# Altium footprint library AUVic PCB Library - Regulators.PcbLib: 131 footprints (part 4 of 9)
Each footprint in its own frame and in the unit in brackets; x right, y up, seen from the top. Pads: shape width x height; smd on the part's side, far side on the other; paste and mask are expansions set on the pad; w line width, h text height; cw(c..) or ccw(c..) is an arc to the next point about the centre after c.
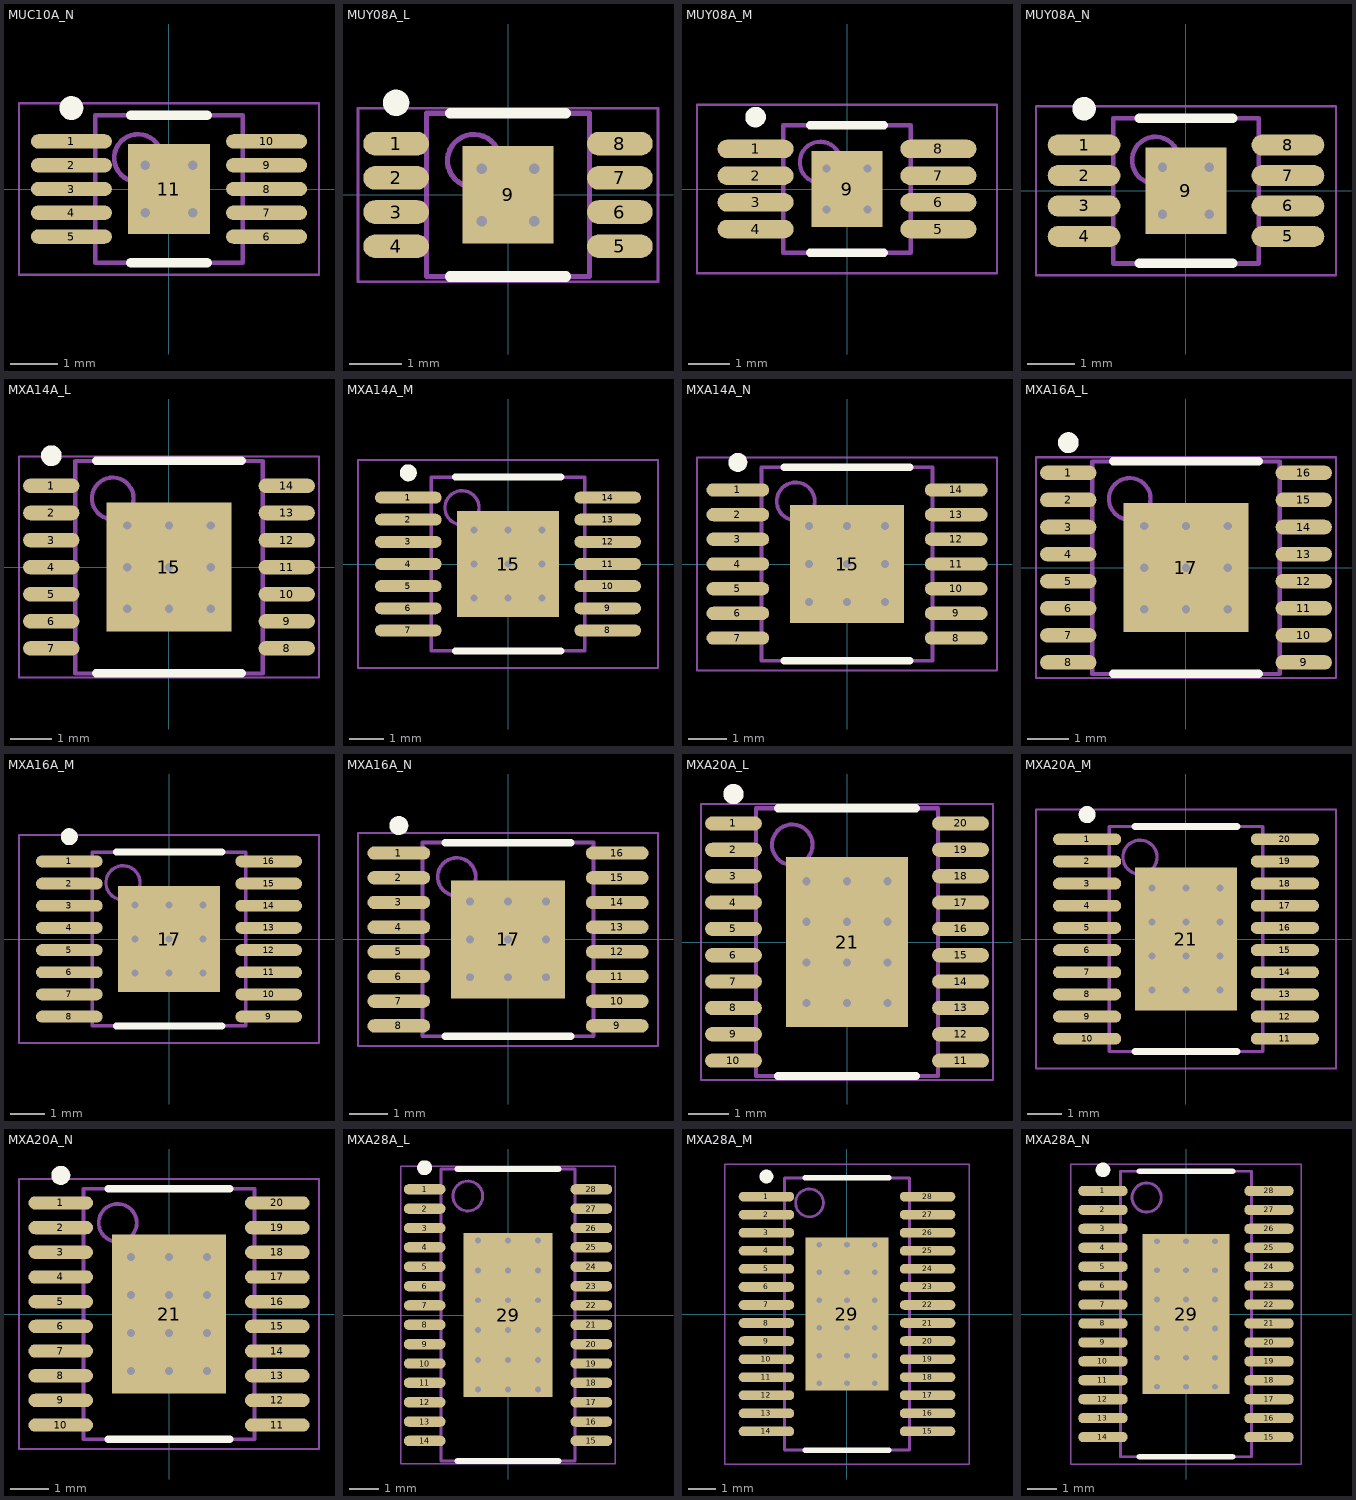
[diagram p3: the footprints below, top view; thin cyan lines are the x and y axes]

## MUC10A_N [mm] "TSSOP, 10-Leads, Body 3x3mm, Pitch 0.5mm, Exposed Pad, IPC Medium Density"
height 1.1
pads (11):
  oval 1.7x0.3 smd: 1(-2.05,1) 2(-2.05,0.5) 3(-2.05,0) 4(-2.05,-0.5) 5(-2.05,-1) 6(2.05,-1) 7(2.05,-0.5) 8(2.05,0) 9(2.05,0.5) 10(2.05,1)
  rect 1.73x1.9 smd: 11(0,0)
via 0.5,-0.5 diameter 0.4 hole 0.2
via -0.5,-0.5 diameter 0.4 hole 0.2
via 0.5,0.5 diameter 0.4 hole 0.2
via -0.5,0.5 diameter 0.4 hole 0.2
Top Overlay:
  circle w0.25: c-2.05,1.7 r0.125
  lines w0.2: -0.8,-1.55 0.8,-1.55 ; -0.8,1.55 0.8,1.55
Mechanical 13:
  circle w0.1: c-0.65,0.65 r0.5
  lines w0.1: -1.55,-1.55 -1.55,1.55 1.55,1.55 1.55,-1.55 -1.55,-1.55
Mechanical 15:
  lines w0.05: -3.15,-1.8 -3.15,1.8 3.15,1.8 3.15,-1.8 -3.15,-1.8
  lines w0.1: -0.5,0 0.5,0 ; 0,-0.5 0,0.5
3D body: height 1.1, standoff 0.05, extent -1.55,-1.55 1.55,1.55

## MUY08A_L [mm] "TSOP, 8-Leads, Body 3x3mm, Pitch 0.65mm, Thermal Pad, IPC High Density"
height 1.09
pads (9):
  oval 1.25x0.45 smd: 1(-2.125,0.975) 2(-2.125,0.325) 3(-2.125,-0.325) 4(-2.125,-0.975) 5(2.125,-0.975) 6(2.125,-0.325) 7(2.125,0.325) 8(2.125,0.975)
  rect 1.73x1.85 smd: 9(0,0)
via -0.5,0.5 diameter 0.4 hole 0.2
via 0.5,0.5 diameter 0.4 hole 0.2
via -0.5,-0.5 diameter 0.4 hole 0.2
via 0.5,-0.5 diameter 0.4 hole 0.2
Top Overlay:
  circle w0.25: c-2.125,1.75 r0.125
  lines w0.2: -1.1,-1.55 1.1,-1.55 ; -1.1,1.55 1.1,1.55
Mechanical 13:
  circle w0.1: c-0.65,0.65 r0.5
  lines w0.1: -1.55,-1.55 -1.55,1.55 1.55,1.55 1.55,-1.55 -1.55,-1.55
Mechanical 15:
  lines w0.05: -2.85,-1.65 -2.85,1.65 2.85,1.65 2.85,-1.65 -2.85,-1.65
  lines w0.1: -0.5,0 0.5,0 ; 0,-0.5 0,0.5
3D body: height 1.09, standoff 0.06, extent -1.55,-1.55 1.55,1.55

## MUY08A_M [mm] "TSOP, 8-Leads, Body 3x3mm, Pitch 0.65mm, Thermal Pad, IPC Low Density"
height 1.09
pads (9):
  oval 1.85x0.45 smd: 1(-2.225,0.975) 2(-2.225,0.325) 3(-2.225,-0.325) 4(-2.225,-0.975) 5(2.225,-0.975) 6(2.225,-0.325) 7(2.225,0.325) 8(2.225,0.975)
  rect 1.73x1.85 smd: 9(0,0)
via -0.5,0.5 diameter 0.4 hole 0.2
via 0.5,0.5 diameter 0.4 hole 0.2
via -0.5,-0.5 diameter 0.4 hole 0.2
via 0.5,-0.5 diameter 0.4 hole 0.2
Top Overlay:
  circle w0.25: c-2.225,1.75 r0.125
  lines w0.2: -0.9,-1.55 0.9,-1.55 ; -0.9,1.55 0.9,1.55
Mechanical 13:
  circle w0.1: c-0.65,0.65 r0.5
  lines w0.1: -1.55,-1.55 -1.55,1.55 1.55,1.55 1.55,-1.55 -1.55,-1.55
Mechanical 15:
  lines w0.05: -3.65,-2.05 -3.65,2.05 3.65,2.05 3.65,-2.05 -3.65,-2.05
  lines w0.1: -0.5,0 0.5,0 ; 0,-0.5 0,0.5
3D body: height 1.09, standoff 0.06, extent -1.55,-1.55 1.55,1.55

## MUY08A_N [mm] "TSOP, 8-Leads, Body 3x3mm, Pitch 0.65mm, Thermal Pad, IPC Medium Density"
height 1.09
pads (9):
  oval 1.55x0.45 smd: 1(-2.175,0.975) 2(-2.175,0.325) 3(-2.175,-0.325) 4(-2.175,-0.975) 5(2.175,-0.975) 6(2.175,-0.325) 7(2.175,0.325) 8(2.175,0.975)
  rect 1.73x1.85 smd: 9(0,0)
via 0.5,-0.5 diameter 0.4 hole 0.2
via -0.5,-0.5 diameter 0.4 hole 0.2
via 0.5,0.5 diameter 0.4 hole 0.2
via -0.5,0.5 diameter 0.4 hole 0.2
Top Overlay:
  circle w0.25: c-2.175,1.75 r0.125
  lines w0.2: -1,-1.55 1,-1.55 ; -1,1.55 1,1.55
Mechanical 13:
  circle w0.1: c-0.65,0.65 r0.5
  lines w0.1: -1.55,-1.55 1.55,-1.55 1.55,1.55 -1.55,1.55 -1.55,-1.55
Mechanical 15:
  lines w0.05: -3.2,-1.8 3.2,-1.8 3.2,1.8 -3.2,1.8 -3.2,-1.8
  lines w0.1: -0.5,0 0.5,0 ; 0,-0.5 0,0.5
3D body: height 1.09, standoff 0.06, extent -1.55,-1.55 1.55,1.55

## MXA14A_L [mm] "TSOP, 14-Leads, Body 5x4.4mm, Pitch 0.65mm, Thermal Pad, IPC High Density"
height 1.1
pads (15):
  oval 1.35x0.35 smd: 1(-2.825,1.95) 2(-2.825,1.3) 3(-2.825,0.65) 4(-2.825,0) 5(-2.825,-0.65) 6(-2.825,-1.3) 7(-2.825,-1.95) 8(2.825,-1.95) 9(2.825,-1.3) 10(2.825,-0.65) 11(2.825,0) 12(2.825,0.65) 13(2.825,1.3) 14(2.825,1.95)
  rect 3x3.1 smd: 15(0,0)
via 1,1 diameter 0.4 hole 0.2
via 1,-1 diameter 0.4 hole 0.2
via 1,0 diameter 0.4 hole 0.2
via -1,1 diameter 0.4 hole 0.2
via 0,1 diameter 0.4 hole 0.2
via 0,-1 diameter 0.4 hole 0.2
via -1,-1 diameter 0.4 hole 0.2
via 0,0 diameter 0.4 hole 0.2
via -1,0 diameter 0.4 hole 0.2
Top Overlay:
  circle w0.25: c-2.825,2.675 r0.125
  lines w0.2: -1.75,-2.55 1.75,-2.55 ; -1.75,2.55 1.75,2.55
Mechanical 13:
  circle w0.1: c-1.35,1.65 r0.5
  lines w0.1: -2.25,-2.55 2.25,-2.55 2.25,2.55 -2.25,2.55 -2.25,-2.55
Mechanical 15:
  lines w0.05: -3.6,-2.65 3.6,-2.65 3.6,2.65 -3.6,2.65 -3.6,-2.65
  lines w0.1: -0.5,0 0.5,0 ; 0,-0.5 0,0.5
3D body: height 1.1, standoff 0.05, extent -2.25,-2.55 2.25,2.55

## MXA14A_M [mm] "TSOP, 14-Leads, Body 5x4.4mm, Pitch 0.65mm, Thermal Pad, IPC Low Density"
height 1.1
pads (15):
  oval 1.95x0.35 smd: 1(-2.925,1.95) 2(-2.925,1.3) 3(-2.925,0.65) 4(-2.925,0) 5(-2.925,-0.65) 6(-2.925,-1.3) 7(-2.925,-1.95) 8(2.925,-1.95) 9(2.925,-1.3) 10(2.925,-0.65) 11(2.925,0) 12(2.925,0.65) 13(2.925,1.3) 14(2.925,1.95)
  rect 3x3.1 smd: 15(0,0)
via -1,0 diameter 0.4 hole 0.2
via 0,0 diameter 0.4 hole 0.2
via -1,-1 diameter 0.4 hole 0.2
via 0,-1 diameter 0.4 hole 0.2
via 0,1 diameter 0.4 hole 0.2
via -1,1 diameter 0.4 hole 0.2
via 1,0 diameter 0.4 hole 0.2
via 1,-1 diameter 0.4 hole 0.2
via 1,1 diameter 0.4 hole 0.2
Top Overlay:
  circle w0.25: c-2.925,2.675 r0.125
  lines w0.2: -1.55,-2.55 1.55,-2.55 ; -1.55,2.55 1.55,2.55
Mechanical 13:
  circle w0.1: c-1.35,1.65 r0.5
  lines w0.1: -2.25,-2.55 -2.25,2.55 2.25,2.55 2.25,-2.55 -2.25,-2.55
Mechanical 15:
  lines w0.05: -4.4,-3.05 -4.4,3.05 4.4,3.05 4.4,-3.05 -4.4,-3.05
  lines w0.1: -0.5,0 0.5,0 ; 0,-0.5 0,0.5
3D body: height 1.1, standoff 0.05, extent -2.25,-2.55 2.25,2.55

## MXA14A_N [mm] "TSOP, 14-Leads, Body 5x4.4mm, Pitch 0.65mm, Thermal Pad, IPC Medium Density"
height 1.1
pads (15):
  oval 1.65x0.35 smd: 1(-2.875,1.95) 2(-2.875,1.3) 3(-2.875,0.65) 4(-2.875,0) 5(-2.875,-0.65) 6(-2.875,-1.3) 7(-2.875,-1.95) 8(2.875,-1.95) 9(2.875,-1.3) 10(2.875,-0.65) 11(2.875,0) 12(2.875,0.65) 13(2.875,1.3) 14(2.875,1.95)
  rect 3x3.1 smd: 15(0,0)
via -1,0 diameter 0.4 hole 0.2
via 0,0 diameter 0.4 hole 0.2
via -1,-1 diameter 0.4 hole 0.2
via 0,-1 diameter 0.4 hole 0.2
via 0,1 diameter 0.4 hole 0.2
via -1,1 diameter 0.4 hole 0.2
via 1,0 diameter 0.4 hole 0.2
via 1,-1 diameter 0.4 hole 0.2
via 1,1 diameter 0.4 hole 0.2
Top Overlay:
  circle w0.25: c-2.875,2.675 r0.125
  lines w0.2: -1.65,-2.55 1.65,-2.55 ; -1.65,2.55 1.65,2.55
Mechanical 13:
  circle w0.1: c-1.35,1.65 r0.5
  lines w0.1: -2.25,-2.55 -2.25,2.55 2.25,2.55 2.25,-2.55 -2.25,-2.55
Mechanical 15:
  lines w0.05: -3.95,-2.8 -3.95,2.8 3.95,2.8 3.95,-2.8 -3.95,-2.8
  lines w0.1: -0.5,0 0.5,0 ; 0,-0.5 0,0.5
3D body: height 1.1, standoff 0.05, extent -2.25,-2.55 2.25,2.55

## MXA16A_L [mm] "TSOP, 16-Leads, Body 5x4.4mm, Pitch 0.65mm, Thermal Pad, IPC High Density"
height 1.1
pads (17):
  oval 1.35x0.35 smd: 1(-2.825,2.275) 2(-2.825,1.625) 3(-2.825,0.975) 4(-2.825,0.325) 5(-2.825,-0.325) 6(-2.825,-0.975) 7(-2.825,-1.625) 8(-2.825,-2.275) 9(2.825,-2.275) 10(2.825,-1.625) 11(2.825,-0.975) 12(2.825,-0.325) 13(2.825,0.325) 14(2.825,0.975) 15(2.825,1.625) 16(2.825,2.275)
  rect 3x3.1 smd: 17(0,0)
via 1,1 diameter 0.4 hole 0.2
via 1,-1 diameter 0.4 hole 0.2
via 1,0 diameter 0.4 hole 0.2
via -1,1 diameter 0.4 hole 0.2
via 0,1 diameter 0.4 hole 0.2
via 0,-1 diameter 0.4 hole 0.2
via -1,-1 diameter 0.4 hole 0.2
via 0,0 diameter 0.4 hole 0.2
via -1,0 diameter 0.4 hole 0.2
Top Overlay:
  circle w0.25: c-2.825,3 r0.125
  lines w0.2: -1.75,-2.55 1.75,-2.55 ; -1.75,2.55 1.75,2.55
Mechanical 13:
  circle w0.1: c-1.35,1.65 r0.5
  lines w0.1: -2.25,-2.55 2.25,-2.55 2.25,2.55 -2.25,2.55 -2.25,-2.55
Mechanical 15:
  lines w0.05: -3.6,-2.65 3.6,-2.65 3.6,2.65 -3.6,2.65 -3.6,-2.65
  lines w0.1: -0.5,0 0.5,0 ; 0,-0.5 0,0.5
3D body: height 1.1, standoff 0.05, extent -2.25,-2.55 2.25,2.55

## MXA16A_M [mm] "TSOP, 16-Leads, Body 5x4.4mm, Pitch 0.65mm, Thermal Pad, IPC Low Density"
height 1.1
pads (17):
  oval 1.95x0.35 smd: 1(-2.925,2.275) 2(-2.925,1.625) 3(-2.925,0.975) 4(-2.925,0.325) 5(-2.925,-0.325) 6(-2.925,-0.975) 7(-2.925,-1.625) 8(-2.925,-2.275) 9(2.925,-2.275) 10(2.925,-1.625) 11(2.925,-0.975) 12(2.925,-0.325) 13(2.925,0.325) 14(2.925,0.975) 15(2.925,1.625) 16(2.925,2.275)
  rect 3x3.1 smd: 17(0,0)
via -1,0 diameter 0.4 hole 0.2
via 0,0 diameter 0.4 hole 0.2
via -1,-1 diameter 0.4 hole 0.2
via 0,-1 diameter 0.4 hole 0.2
via 0,1 diameter 0.4 hole 0.2
via -1,1 diameter 0.4 hole 0.2
via 1,0 diameter 0.4 hole 0.2
via 1,-1 diameter 0.4 hole 0.2
via 1,1 diameter 0.4 hole 0.2
Top Overlay:
  circle w0.25: c-2.925,3 r0.125
  lines w0.2: -1.55,-2.55 1.55,-2.55 ; -1.55,2.55 1.55,2.55
Mechanical 13:
  circle w0.1: c-1.35,1.65 r0.5
  lines w0.1: -2.25,-2.55 -2.25,2.55 2.25,2.55 2.25,-2.55 -2.25,-2.55
Mechanical 15:
  lines w0.05: -4.4,-3.05 -4.4,3.05 4.4,3.05 4.4,-3.05 -4.4,-3.05
  lines w0.1: -0.5,0 0.5,0 ; 0,-0.5 0,0.5
3D body: height 1.1, standoff 0.05, extent -2.25,-2.55 2.25,2.55

## MXA16A_N [mm] "TSOP, 16-Leads, Body 5x4.4mm, Pitch 0.65mm, Thermal Pad, IPC Medium Density"
height 1.1
pads (17):
  oval 1.65x0.35 smd: 1(-2.875,2.275) 2(-2.875,1.625) 3(-2.875,0.975) 4(-2.875,0.325) 5(-2.875,-0.325) 6(-2.875,-0.975) 7(-2.875,-1.625) 8(-2.875,-2.275) 9(2.875,-2.275) 10(2.875,-1.625) 11(2.875,-0.975) 12(2.875,-0.325) 13(2.875,0.325) 14(2.875,0.975) 15(2.875,1.625) 16(2.875,2.275)
  rect 3x3.1 smd: 17(0,0)
via -1,0 diameter 0.4 hole 0.2
via 0,0 diameter 0.4 hole 0.2
via -1,-1 diameter 0.4 hole 0.2
via 0,-1 diameter 0.4 hole 0.2
via 0,1 diameter 0.4 hole 0.2
via -1,1 diameter 0.4 hole 0.2
via 1,0 diameter 0.4 hole 0.2
via 1,-1 diameter 0.4 hole 0.2
via 1,1 diameter 0.4 hole 0.2
Top Overlay:
  circle w0.25: c-2.875,3 r0.125
  lines w0.2: -1.65,-2.55 1.65,-2.55 ; -1.65,2.55 1.65,2.55
Mechanical 13:
  circle w0.1: c-1.35,1.65 r0.5
  lines w0.1: -2.25,-2.55 -2.25,2.55 2.25,2.55 2.25,-2.55 -2.25,-2.55
Mechanical 15:
  lines w0.05: -3.95,-2.8 -3.95,2.8 3.95,2.8 3.95,-2.8 -3.95,-2.8
  lines w0.1: -0.5,0 0.5,0 ; 0,-0.5 0,0.5
3D body: height 1.1, standoff 0.05, extent -2.25,-2.55 2.25,2.55

## MXA20A_L [mm] "TSOP, 20-Leads, Body 6.5x4.4mm, Pitch 0.65mm, Thermal Pad, IPC High Density"
height 1.1
pads (21):
  oval 1.4x0.35 smd: 1(-2.8,2.925) 2(-2.8,2.275) 3(-2.8,1.625) 4(-2.8,0.975) 5(-2.8,0.325) 6(-2.8,-0.325) 7(-2.8,-0.975) 8(-2.8,-1.625) 9(-2.8,-2.275) 10(-2.8,-2.925) 11(2.8,-2.925) 12(2.8,-2.275) 13(2.8,-1.625) 14(2.8,-0.975) 15(2.8,-0.325) 16(2.8,0.325) 17(2.8,0.975) 18(2.8,1.625) 19(2.8,2.275) 20(2.8,2.925)
  rect 3x4.2 smd: 21(0,0)
via 0,1.5 diameter 0.5 hole 0.2
via 1,1.5 diameter 0.5 hole 0.2
via -1,1.5 diameter 0.5 hole 0.2
via -1,0.5 diameter 0.5 hole 0.2
via -1,-0.5 diameter 0.5 hole 0.2
via -1,-1.5 diameter 0.5 hole 0.2
via 1,-1.5 diameter 0.5 hole 0.2
via 0,-1.5 diameter 0.5 hole 0.2
via 1,-0.5 diameter 0.5 hole 0.2
via 0,-0.5 diameter 0.5 hole 0.2
via 1,0.5 diameter 0.5 hole 0.2
via 0,0.5 diameter 0.5 hole 0.2
Top Overlay:
  circle w0.25: c-2.8,3.65 r0.125
  lines w0.2: -1.7,-3.3 1.7,-3.3 ; -1.7,3.3 1.7,3.3
Mechanical 13:
  circle w0.1: c-1.35,2.4 r0.5
  lines w0.1: -2.25,-3.3 -2.25,3.3 2.25,3.3 2.25,-3.3 -2.25,-3.3
Mechanical 15:
  lines w0.05: -3.6,-3.4 -3.6,3.4 3.6,3.4 3.6,-3.4 -3.6,-3.4
  lines w0.1: -0.5,0 0.5,0 ; 0,-0.5 0,0.5
3D body: height 1.1, standoff 0.05, extent -2.25,-3.3 2.25,3.3

## MXA20A_M [mm] "TSOP, 20-Leads, Body 6.5x4.4mm, Pitch 0.65mm, Thermal Pad, IPC Low Density"
height 1.1
pads (21):
  oval 2x0.35 smd: 1(-2.9,2.925) 2(-2.9,2.275) 3(-2.9,1.625) 4(-2.9,0.975) 5(-2.9,0.325) 6(-2.9,-0.325) 7(-2.9,-0.975) 8(-2.9,-1.625) 9(-2.9,-2.275) 10(-2.9,-2.925) 11(2.9,-2.925) 12(2.9,-2.275) 13(2.9,-1.625) 14(2.9,-0.975) 15(2.9,-0.325) 16(2.9,0.325) 17(2.9,0.975) 18(2.9,1.625) 19(2.9,2.275) 20(2.9,2.925)
  rect 3x4.2 smd: 21(0,0)
via 0,0.5 diameter 0.5 hole 0.2
via 1,0.5 diameter 0.5 hole 0.2
via 0,-0.5 diameter 0.5 hole 0.2
via 1,-0.5 diameter 0.5 hole 0.2
via 0,-1.5 diameter 0.5 hole 0.2
via 1,-1.5 diameter 0.5 hole 0.2
via -1,-1.5 diameter 0.5 hole 0.2
via -1,-0.5 diameter 0.5 hole 0.2
via -1,0.5 diameter 0.5 hole 0.2
via -1,1.5 diameter 0.5 hole 0.2
via 1,1.5 diameter 0.5 hole 0.2
via 0,1.5 diameter 0.5 hole 0.2
Top Overlay:
  circle w0.25: c-2.9,3.65 r0.125
  lines w0.2: -1.5,-3.3 1.5,-3.3 ; -1.5,3.3 1.5,3.3
Mechanical 13:
  circle w0.1: c-1.35,2.4 r0.5
  lines w0.1: -2.25,-3.3 2.25,-3.3 2.25,3.3 -2.25,3.3 -2.25,-3.3
Mechanical 15:
  lines w0.05: -4.4,-3.8 4.4,-3.8 4.4,3.8 -4.4,3.8 -4.4,-3.8
  lines w0.1: -0.5,0 0.5,0 ; 0,-0.5 0,0.5
3D body: height 1.1, standoff 0.05, extent -2.25,-3.3 2.25,3.3

## MXA20A_N [mm] "TSOP, 20-Leads, Body 6.5x4.4mm, Pitch 0.65mm, Thermal Pad, IPC Medium Density"
height 1.1
pads (21):
  oval 1.7x0.35 smd: 1(-2.85,2.925) 2(-2.85,2.275) 3(-2.85,1.625) 4(-2.85,0.975) 5(-2.85,0.325) 6(-2.85,-0.325) 7(-2.85,-0.975) 8(-2.85,-1.625) 9(-2.85,-2.275) 10(-2.85,-2.925) 11(2.85,-2.925) 12(2.85,-2.275) 13(2.85,-1.625) 14(2.85,-0.975) 15(2.85,-0.325) 16(2.85,0.325) 17(2.85,0.975) 18(2.85,1.625) 19(2.85,2.275) 20(2.85,2.925)
  rect 3x4.2 smd: 21(0,0)
via 0,1.5 diameter 0.5 hole 0.2
via 1,1.5 diameter 0.5 hole 0.2
via -1,1.5 diameter 0.5 hole 0.2
via -1,0.5 diameter 0.5 hole 0.2
via -1,-0.5 diameter 0.5 hole 0.2
via -1,-1.5 diameter 0.5 hole 0.2
via 1,-1.5 diameter 0.5 hole 0.2
via 0,-1.5 diameter 0.5 hole 0.2
via 1,-0.5 diameter 0.5 hole 0.2
via 0,-0.5 diameter 0.5 hole 0.2
via 1,0.5 diameter 0.5 hole 0.2
via 0,0.5 diameter 0.5 hole 0.2
Top Overlay:
  circle w0.25: c-2.85,3.65 r0.125
  lines w0.2: -1.6,-3.3 1.6,-3.3 ; -1.6,3.3 1.6,3.3
Mechanical 13:
  circle w0.1: c-1.35,2.4 r0.5
  lines w0.1: -2.25,-3.3 2.25,-3.3 2.25,3.3 -2.25,3.3 -2.25,-3.3
Mechanical 15:
  lines w0.05: -3.95,-3.55 3.95,-3.55 3.95,3.55 -3.95,3.55 -3.95,-3.55
  lines w0.1: -0.5,0 0.5,0 ; 0,-0.5 0,0.5
3D body: height 1.1, standoff 0.05, extent -2.25,-3.3 2.25,3.3

## MXA28A_L [mm] "TSOP, 28-Leads, Body 9.7x4.4mm, Pitch 0.65mm, Thermal Pad, IPC High Density"
height 1.1
pads (29):
  oval 1.4x0.35 smd: 1(-2.8,4.225) 2(-2.8,3.575) 3(-2.8,2.925) 4(-2.8,2.275) 5(-2.8,1.625) 6(-2.8,0.975) 7(-2.8,0.325) 8(-2.8,-0.325) 9(-2.8,-0.975) 10(-2.8,-1.625) 11(-2.8,-2.275) 12(-2.8,-2.925) 13(-2.8,-3.575) 14(-2.8,-4.225) 15(2.8,-4.225) 16(2.8,-3.575) 17(2.8,-2.925) 18(2.8,-2.275) 19(2.8,-1.625) 20(2.8,-0.975) 21(2.8,-0.325) 22(2.8,0.325) 23(2.8,0.975) 24(2.8,1.625) 25(2.8,2.275) 26(2.8,2.925) 27(2.8,3.575) 28(2.8,4.225)
  rect 3x5.5 smd: 29(0,0)
via 0,0.5 diameter 0.4 hole 0.2
via 1,0.5 diameter 0.4 hole 0.2
via 0,-0.5 diameter 0.4 hole 0.2
via 1,-0.5 diameter 0.4 hole 0.2
via 0,-1.5 diameter 0.4 hole 0.2
via 1,-1.5 diameter 0.4 hole 0.2
via 1,1.5 diameter 0.4 hole 0.2
via 0,1.5 diameter 0.4 hole 0.2
via 1,-2.5 diameter 0.4 hole 0.2
via 0,-2.5 diameter 0.4 hole 0.2
via -1,-2.5 diameter 0.4 hole 0.2
via -1,1.5 diameter 0.4 hole 0.2
via -1,-1.5 diameter 0.4 hole 0.2
via -1,-0.5 diameter 0.4 hole 0.2
via -1,0.5 diameter 0.4 hole 0.2
via -1,2.5 diameter 0.4 hole 0.2
via 0,2.5 diameter 0.4 hole 0.2
via 1,2.5 diameter 0.4 hole 0.2
Top Overlay:
  circle w0.25: c-2.8,4.95 r0.125
  lines w0.2: -1.7,-4.9 1.7,-4.9 ; -1.7,4.9 1.7,4.9
Mechanical 13:
  circle w0.1: c-1.35,4 r0.5
  lines w0.1: -2.25,-4.9 2.25,-4.9 2.25,4.9 -2.25,4.9 -2.25,-4.9
Mechanical 15:
  lines w0.05: -3.6,-5 3.6,-5 3.6,5 -3.6,5 -3.6,-5
  lines w0.1: -0.5,0 0.5,0 ; 0,-0.5 0,0.5
3D body: height 1.1, standoff 0.05, extent -2.25,-4.9 2.25,4.9

## MXA28A_M [mm] "TSOP, 28-Leads, Body 9.7x4.4mm, Pitch 0.65mm, Thermal Pad, IPC Low Density"
height 1.1
pads (29):
  oval 2x0.35 smd: 1(-2.9,4.225) 2(-2.9,3.575) 3(-2.9,2.925) 4(-2.9,2.275) 5(-2.9,1.625) 6(-2.9,0.975) 7(-2.9,0.325) 8(-2.9,-0.325) 9(-2.9,-0.975) 10(-2.9,-1.625) 11(-2.9,-2.275) 12(-2.9,-2.925) 13(-2.9,-3.575) 14(-2.9,-4.225) 15(2.9,-4.225) 16(2.9,-3.575) 17(2.9,-2.925) 18(2.9,-2.275) 19(2.9,-1.625) 20(2.9,-0.975) 21(2.9,-0.325) 22(2.9,0.325) 23(2.9,0.975) 24(2.9,1.625) 25(2.9,2.275) 26(2.9,2.925) 27(2.9,3.575) 28(2.9,4.225)
  rect 3x5.5 smd: 29(0,0)
via 0,0.5 diameter 0.4 hole 0.2
via 1,0.5 diameter 0.4 hole 0.2
via 0,-0.5 diameter 0.4 hole 0.2
via 1,-0.5 diameter 0.4 hole 0.2
via 0,-1.5 diameter 0.4 hole 0.2
via 1,-1.5 diameter 0.4 hole 0.2
via 1,1.5 diameter 0.4 hole 0.2
via 0,1.5 diameter 0.4 hole 0.2
via 1,-2.5 diameter 0.4 hole 0.2
via 0,-2.5 diameter 0.4 hole 0.2
via -1,-2.5 diameter 0.4 hole 0.2
via -1,1.5 diameter 0.4 hole 0.2
via -1,-1.5 diameter 0.4 hole 0.2
via -1,-0.5 diameter 0.4 hole 0.2
via -1,0.5 diameter 0.4 hole 0.2
via -1,2.5 diameter 0.4 hole 0.2
via 0,2.5 diameter 0.4 hole 0.2
via 1,2.5 diameter 0.4 hole 0.2
Top Overlay:
  circle w0.25: c-2.9,4.95 r0.125
  lines w0.2: -1.5,-4.9 1.5,-4.9 ; -1.5,4.9 1.5,4.9
Mechanical 13:
  circle w0.1: c-1.35,4 r0.5
  lines w0.1: -2.25,-4.9 -2.25,4.9 2.25,4.9 2.25,-4.9 -2.25,-4.9
Mechanical 15:
  lines w0.05: -4.4,-5.4 -4.4,5.4 4.4,5.4 4.4,-5.4 -4.4,-5.4
  lines w0.1: -0.5,0 0.5,0 ; 0,-0.5 0,0.5
3D body: height 1.1, standoff 0.05, extent -2.25,-4.9 2.25,4.9

## MXA28A_N [mm] "TSOP, 28-Leads, Body 9.7x4.4mm, Pitch 0.65mm, Thermal Pad, IPC Medium Density"
height 1.1
pads (29):
  oval 1.7x0.35 smd: 1(-2.85,4.225) 2(-2.85,3.575) 3(-2.85,2.925) 4(-2.85,2.275) 5(-2.85,1.625) 6(-2.85,0.975) 7(-2.85,0.325) 8(-2.85,-0.325) 9(-2.85,-0.975) 10(-2.85,-1.625) 11(-2.85,-2.275) 12(-2.85,-2.925) 13(-2.85,-3.575) 14(-2.85,-4.225) 15(2.85,-4.225) 16(2.85,-3.575) 17(2.85,-2.925) 18(2.85,-2.275) 19(2.85,-1.625) 20(2.85,-0.975) 21(2.85,-0.325) 22(2.85,0.325) 23(2.85,0.975) 24(2.85,1.625) 25(2.85,2.275) 26(2.85,2.925) 27(2.85,3.575) 28(2.85,4.225)
  rect 3x5.5 smd: 29(0,0)
via 0,0.5 diameter 0.4 hole 0.2
via 1,0.5 diameter 0.4 hole 0.2
via 0,-0.5 diameter 0.4 hole 0.2
via 1,-0.5 diameter 0.4 hole 0.2
via 0,-1.5 diameter 0.4 hole 0.2
via 1,-1.5 diameter 0.4 hole 0.2
via 1,1.5 diameter 0.4 hole 0.2
via 0,1.5 diameter 0.4 hole 0.2
via 1,-2.5 diameter 0.4 hole 0.2
via 0,-2.5 diameter 0.4 hole 0.2
via -1,-2.5 diameter 0.4 hole 0.2
via -1,1.5 diameter 0.4 hole 0.2
via -1,-1.5 diameter 0.4 hole 0.2
via -1,-0.5 diameter 0.4 hole 0.2
via -1,0.5 diameter 0.4 hole 0.2
via -1,2.5 diameter 0.4 hole 0.2
via 0,2.5 diameter 0.4 hole 0.2
via 1,2.5 diameter 0.4 hole 0.2
Top Overlay:
  circle w0.25: c-2.85,4.95 r0.125
  lines w0.2: -1.6,-4.9 1.6,-4.9 ; -1.6,4.9 1.6,4.9
Mechanical 13:
  circle w0.1: c-1.35,4 r0.5
  lines w0.1: -2.25,-4.9 2.25,-4.9 2.25,4.9 -2.25,4.9 -2.25,-4.9
Mechanical 15:
  lines w0.05: -3.95,-5.15 3.95,-5.15 3.95,5.15 -3.95,5.15 -3.95,-5.15
  lines w0.1: -0.5,0 0.5,0 ; 0,-0.5 0,0.5
3D body: height 1.1, standoff 0.05, extent -2.25,-4.9 2.25,4.9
